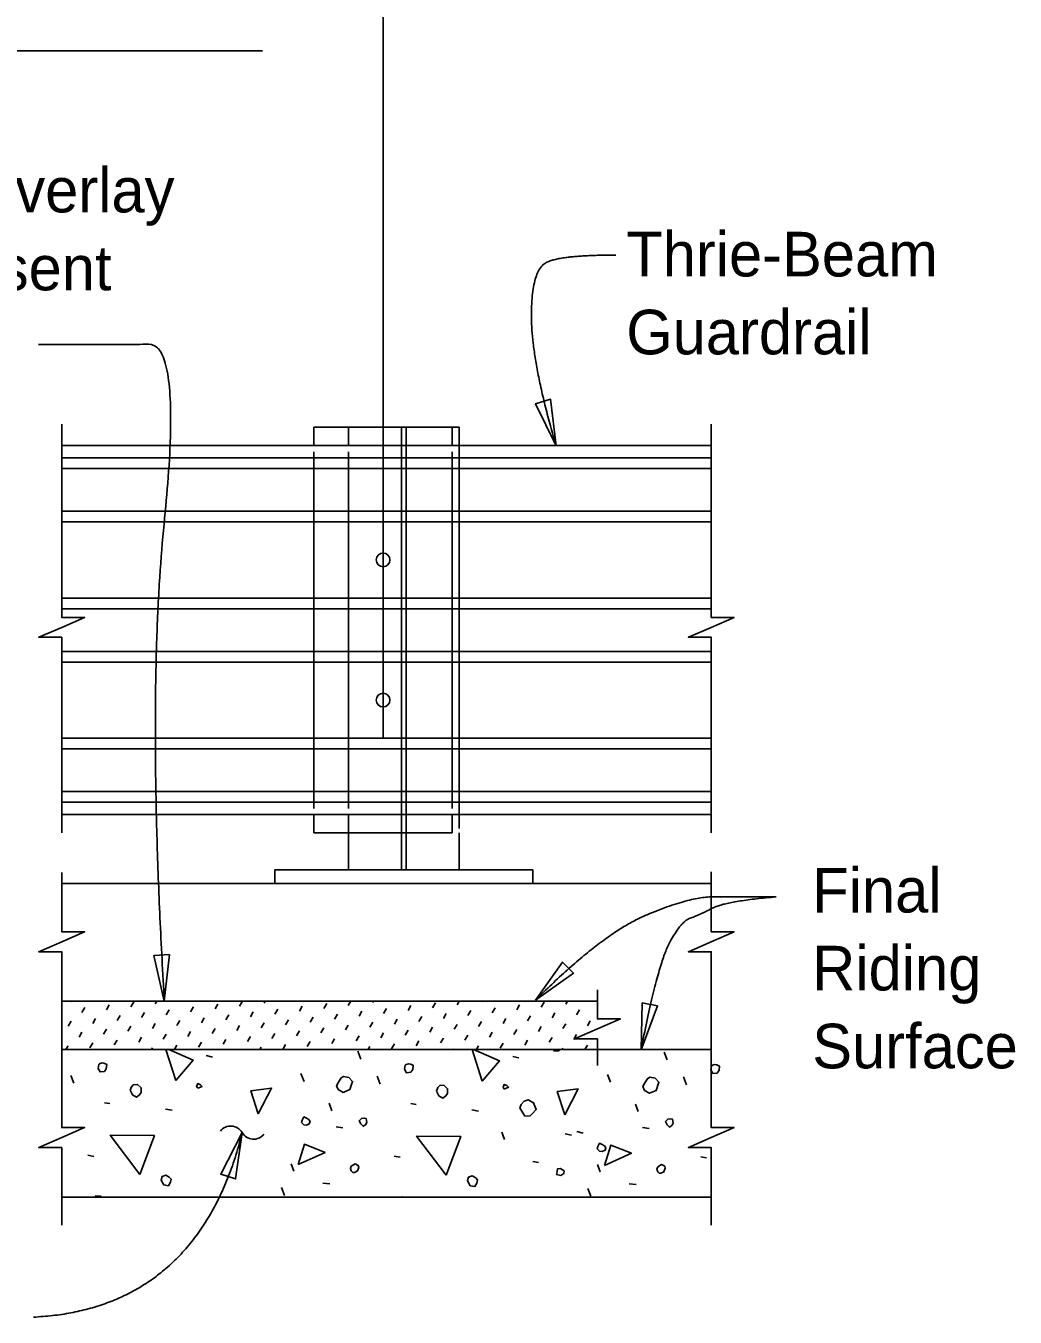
# Model space of a CAD drawing. Extents: x 21516.9 to 21589, y 56154.7 to 56194.3.
# Drawn here: x 21532.46 to 21536.94, y 56170.16 to 56176 of the extents above; entities that cross this region are included whole.
import ezdxf

# ---------------------------------------------------------------- set-up
doc = ezdxf.new("R2010")
doc.units = 0
for name, color, linetype in [('AdhocPoint_dp', 7, 'Continuous'), ('Border', 7, 'Continuous'), ('Patterning', 7, 'Continuous'), ('PlotBorder_dp', 7, 'Continuous'), ('TextMisc', 7, 'Continuous')]:
    doc.layers.add(name, color=color, linetype=linetype)

msp = doc.modelspace()

# ---------------------------------------------------------------- linework, layer by layer
at = {"layer": 'AdhocPoint_dp'}
for p, q in [((21532.6268, 56172.1237), (21535.5624, 56172.1237)), ((21535.0481, 56171.5927), (21532.6268, 56171.5927)), ((21535.5624, 56171.3737), (21532.6268, 56171.3737)), ((21532.6268, 56170.707), (21535.5624, 56170.707))]:
    msp.add_line(p, q, dxfattribs=at)
at = {"layer": 'Border'}
for p, q in [((21534.1627, 56172.1863), (21534.1627, 56174.1863)), ((21534.1835, 56172.1863), (21534.1835, 56174.1863)), ((21534.4231, 56174.1863), (21534.4231, 56172.3733)), ((21533.9231, 56174.0744), (21533.9231, 56172.4625))]:
    msp.add_line(p, q, dxfattribs=at)
at = {"layer": 'Patterning'}
for p, q in [((21533.7668, 56174.1863), (21534.3918, 56174.1863)), ((21533.7668, 56174.1863), (21533.7668, 56174.1029)), ((21534.3918, 56174.1863), (21534.3918, 56174.1029)), ((21533.7668, 56174.0744), (21533.7668, 56172.4625)), ((21534.3918, 56174.0744), (21534.3918, 56172.4625)), ((21533.7668, 56172.3529), (21533.7668, 56172.4363)), ((21534.3918, 56172.3529), (21534.3918, 56172.4363)), ((21533.7668, 56172.3529), (21534.3918, 56172.3529)), ((21532.6693, 56171.5899), (21532.6709, 56171.5927)), ((21532.7181, 56171.5411), (21532.7311, 56171.5635)), ((21532.8287, 56171.554), (21532.8417, 56171.5764)), ((21532.9394, 56171.567), (21532.9523, 56171.5894)), ((21533.05, 56171.58), (21533.0573, 56171.5927)), ((21533.2095, 56171.5441), (21533.2224, 56171.5665)), ((21533.3201, 56171.5571), (21533.3331, 56171.5794)), ((21533.4307, 56171.57), (21533.4437, 56171.5924)), ((21533.5414, 56171.583), (21533.547, 56171.5927)), ((21533.5902, 56171.5341), (21533.6032, 56171.5565)), ((21533.7008, 56171.5471), (21533.7138, 56171.5695)), ((21533.8115, 56171.5601), (21533.8244, 56171.5825)), ((21533.9221, 56171.573), (21533.9335, 56171.5927)), ((21534.0327, 56171.586), (21534.0366, 56171.5927)), ((21534.0816, 56171.5372), (21534.0945, 56171.5596)), ((21534.1922, 56171.5501), (21534.2052, 56171.5725)), ((21534.3028, 56171.5631), (21534.3158, 56171.5855)), ((21534.4135, 56171.5761), (21534.4231, 56171.5927)), ((21534.5241, 56171.589), (21534.5262, 56171.5927)), ((21534.5729, 56171.5402), (21534.5859, 56171.5626)), ((21534.6836, 56171.5532), (21534.6965, 56171.5755)), ((21534.7942, 56171.5661), (21534.8072, 56171.5885)), ((21534.9048, 56171.5791), (21534.9127, 56171.5927)), ((21535.0155, 56171.592), (21535.0158, 56171.5927)), ((21532.6563, 56171.4793), (21532.6693, 56171.5017)), ((21532.7669, 56171.4922), (21532.7799, 56171.5146)), ((21532.8776, 56171.5052), (21532.8905, 56171.5276)), ((21532.9882, 56171.5182), (21533.0012, 56171.5406)), ((21533.0988, 56171.5311), (21533.1118, 56171.5535)), ((21533.1477, 56171.4823), (21533.1606, 56171.5047)), ((21533.2583, 56171.4953), (21533.2713, 56171.5176)), ((21533.3689, 56171.5082), (21533.3819, 56171.5306)), ((21533.4796, 56171.5212), (21533.4925, 56171.5436)), ((21533.639, 56171.4853), (21533.652, 56171.5077)), ((21533.7497, 56171.4983), (21533.7626, 56171.5207)), ((21533.8603, 56171.5112), (21533.8733, 56171.5336)), ((21533.9709, 56171.5242), (21533.9839, 56171.5466)), ((21534.0198, 56171.4754), (21534.0327, 56171.4978)), ((21534.1304, 56171.4883), (21534.1434, 56171.5107)), ((21534.241, 56171.5013), (21534.254, 56171.5237)), ((21534.3517, 56171.5143), (21534.3646, 56171.5367)), ((21534.4623, 56171.5272), (21534.4753, 56171.5496)), ((21534.5111, 56171.4784), (21534.5241, 56171.5008)), ((21534.6218, 56171.4914), (21534.6347, 56171.5137)), ((21534.7324, 56171.5043), (21534.7454, 56171.5267)), ((21534.843, 56171.5173), (21534.856, 56171.5397)), ((21534.9537, 56171.5302), (21534.9666, 56171.5526)), ((21535.0025, 56171.4814), (21535.0155, 56171.5038)), ((21532.7051, 56171.4304), (21532.7181, 56171.4528)), ((21532.8158, 56171.4434), (21532.8287, 56171.4658)), ((21532.9264, 56171.4564), (21532.9394, 56171.4788)), ((21533.037, 56171.4693), (21533.05, 56171.4917)), ((21533.0859, 56171.4205), (21533.0988, 56171.4429)), ((21533.1965, 56171.4335), (21533.2095, 56171.4558)), ((21533.3071, 56171.4464), (21533.3201, 56171.4688)), ((21533.4178, 56171.4594), (21533.4307, 56171.4818)), ((21533.5284, 56171.4723), (21533.5414, 56171.4947)), ((21533.5772, 56171.4235), (21533.5902, 56171.4459)), ((21533.6879, 56171.4365), (21533.7008, 56171.4589)), ((21533.7985, 56171.4494), (21533.8115, 56171.4718)), ((21533.9091, 56171.4624), (21533.9221, 56171.4848)), ((21534.0686, 56171.4265), (21534.0816, 56171.4489)), ((21534.1792, 56171.4395), (21534.1922, 56171.4619)), ((21534.2899, 56171.4525), (21534.3028, 56171.4749)), ((21534.4005, 56171.4654), (21534.4135, 56171.4878)), ((21534.4493, 56171.4166), (21534.4623, 56171.439)), ((21534.56, 56171.4296), (21534.5729, 56171.4519)), ((21534.6706, 56171.4425), (21534.6836, 56171.4649)), ((21534.7812, 56171.4555), (21534.7942, 56171.4779)), ((21534.8919, 56171.4684), (21534.9048, 56171.4908)), ((21534.9407, 56171.4196), (21534.9537, 56171.442)), ((21532.6463, 56171.3737), (21532.6563, 56171.391)), ((21532.754, 56171.3816), (21532.7669, 56171.404)), ((21532.8646, 56171.3946), (21532.8776, 56171.417)), ((21532.9752, 56171.4075), (21532.9882, 56171.4299)), ((21533.0328, 56171.3737), (21533.037, 56171.3811)), ((21533.1359, 56171.3738), (21533.1477, 56171.3941)), ((21533.2453, 56171.3846), (21533.2583, 56171.407)), ((21533.356, 56171.3976), (21533.3689, 56171.42)), ((21533.4666, 56171.4106), (21533.4796, 56171.4329)), ((21533.5224, 56171.3738), (21533.5284, 56171.3841)), ((21533.6261, 56171.3747), (21533.639, 56171.3971)), ((21533.7367, 56171.3876), (21533.7497, 56171.41)), ((21533.8473, 56171.4006), (21533.8603, 56171.423)), ((21533.958, 56171.4136), (21533.9709, 56171.436)), ((21534.0121, 56171.3739), (21534.0198, 56171.3871)), ((21534.1174, 56171.3777), (21534.1304, 56171.4001)), ((21534.2281, 56171.3907), (21534.241, 56171.4131)), ((21534.3387, 56171.4036), (21534.3517, 56171.426)), ((21534.5017, 56171.3739), (21534.5111, 56171.3901)), ((21534.6088, 56171.3807), (21534.6218, 56171.4031)), ((21534.7194, 56171.3937), (21534.7324, 56171.4161)), ((21534.8301, 56171.4066), (21534.843, 56171.429)), ((21534.8883, 56171.374), (21534.8919, 56171.3802)), ((21534.9914, 56171.374), (21535.0025, 56171.3932)), ((21533.2803, 56171.3465), (21533.3086, 56171.3395)), ((21533.909, 56171.3739), (21533.9091, 56171.3742)), ((21533.9786, 56171.3306), (21533.9645, 56171.366)), ((21534.3986, 56171.3739), (21534.4005, 56171.3772)), ((21534.665, 56171.343), (21534.6933, 56171.3359)), ((21535.3633, 56171.3271), (21535.3491, 56171.3624)), ((21533.7223, 56171.2299), (21533.7081, 56171.2652)), ((21532.6817, 56171.2217), (21532.6675, 56171.257)), ((21534.0664, 56171.2181), (21534.0522, 56171.2535)), ((21535.107, 56171.2263), (21535.0928, 56171.2617)), ((21535.451, 56171.2146), (21535.4369, 56171.2499)), ((21532.8196, 56171.1333), (21532.8443, 56171.1297)), ((21533.0953, 56171.105), (21533.1254, 56171.0997)), ((21533.8478, 56171.0973), (21533.8354, 56171.1309)), ((21534.2043, 56171.1297), (21534.229, 56171.1262)), ((21534.48, 56171.1014), (21534.5101, 56171.0961)), ((21535.2325, 56171.0937), (21535.2201, 56171.1273)), ((21533.8666, 56171.0254), (21533.8967, 56171.0201)), ((21534.6285, 56170.9671), (21534.6161, 56171.0007)), ((21534.9025, 56170.9936), (21534.9308, 56170.9865)), ((21534.9549, 56171.0036), (21534.9832, 56170.9965)), ((21535.2513, 56171.0219), (21535.2813, 56171.0166)), ((21532.7453, 56170.8964), (21532.7718, 56170.8911)), ((21533.6763, 56170.8245), (21533.6639, 56170.8581)), ((21534.13, 56170.8928), (21534.1565, 56170.8875)), ((21534.7558, 56170.8681), (21534.7823, 56170.8628)), ((21535.5147, 56170.8893), (21535.5412, 56170.884)), ((21535.061, 56170.821), (21535.0486, 56170.8546)), ((21533.6339, 56170.7149), (21533.6197, 56170.7503)), ((21533.8065, 56170.7709), (21533.8383, 56170.7673)), ((21535.0186, 56170.7114), (21535.0044, 56170.7467)), ((21535.1912, 56170.7673), (21535.223, 56170.7638))]:
    msp.add_line(p, q, dxfattribs=at)
for points in [[(21533.1431, 56171.234), (21533.0976, 56171.3737)], [(21533.1115, 56171.3737), (21533.2209, 56171.326), (21533.1431, 56171.234)], [(21534.5278, 56171.2305), (21534.4812, 56171.3737)], [(21534.4881, 56171.3737), (21534.6055, 56171.3224), (21534.5278, 56171.2305)], [(21534.8499, 56171.3737), (21534.8524, 56171.3678), (21534.8489, 56171.3713)], [(21534.8524, 56171.3678), (21534.8736, 56171.3678), (21534.8796, 56171.3737)], [(21532.7913, 56171.2888), (21532.8001, 56171.2729), (21532.8196, 56171.2747), (21532.8284, 56171.2871), (21532.8302, 56171.3065), (21532.8178, 56171.3118), (21532.809, 56171.3136), (21532.7984, 56171.31), (21532.7948, 56171.3065), (21532.7913, 56171.2888)], [(21534.176, 56171.2853), (21534.1848, 56171.2694), (21534.2043, 56171.2712), (21534.2131, 56171.2835), (21534.2149, 56171.303), (21534.2025, 56171.3083), (21534.1936, 56171.31), (21534.183, 56171.3065), (21534.1795, 56171.303), (21534.176, 56171.2853)], [(21535.5606, 56171.2818), (21535.5695, 56171.2658), (21535.5889, 56171.2676), (21535.5978, 56171.28), (21535.5995, 56171.2994), (21535.5872, 56171.3047), (21535.5783, 56171.3065), (21535.5677, 56171.303), (21535.5642, 56171.2994), (21535.5606, 56171.2818)], [(21532.9362, 56171.1898), (21532.9469, 56171.1686), (21532.9645, 56171.158), (21532.9787, 56171.1686), (21532.9857, 56171.1792), (21532.9857, 56171.2004), (21532.9698, 56171.2163), (21532.9504, 56171.2146), (21532.9416, 56171.2057), (21532.9362, 56171.1898)], [(21533.2421, 56171.1987), (21533.2615, 56171.2075), (21533.2544, 56171.2146), (21533.2421, 56171.2199), (21533.2368, 56171.2075), (21533.2421, 56171.1987)], [(21533.8761, 56171.1927), (21533.8991, 56171.1804), (21533.9291, 56171.1927), (21533.9415, 56171.2299), (21533.9238, 56171.2475), (21533.9008, 56171.2528), (21533.8902, 56171.2458), (21533.8778, 56171.2263), (21533.869, 56171.2104), (21533.8761, 56171.1927)], [(21534.3209, 56171.1863), (21534.3315, 56171.1651), (21534.3492, 56171.1545), (21534.3634, 56171.1651), (21534.3704, 56171.1757), (21534.3704, 56171.1969), (21534.3545, 56171.2128), (21534.3351, 56171.211), (21534.3262, 56171.2022), (21534.3209, 56171.1863)], [(21534.6268, 56171.1951), (21534.6462, 56171.204), (21534.6391, 56171.211), (21534.6268, 56171.2163), (21534.6214, 56171.204), (21534.6268, 56171.1951)], [(21535.2608, 56171.1892), (21535.2837, 56171.1768), (21535.3138, 56171.1892), (21535.3262, 56171.2263), (21535.3085, 56171.244), (21535.2855, 56171.2493), (21535.2749, 56171.2422), (21535.2625, 56171.2228), (21535.2537, 56171.2069), (21535.2608, 56171.1892)], [(21533.5155, 56171.0831), (21533.4819, 56171.1874), (21533.5756, 56171.1998), (21533.5155, 56171.0831)], [(21534.6975, 56171.1103), (21534.7204, 56171.0732), (21534.7434, 56171.0749), (21534.7523, 56171.0838), (21534.7717, 56171.1032), (21534.7593, 56171.1333), (21534.7346, 56171.1474), (21534.7169, 56171.1403), (21534.7028, 56171.1262), (21534.6975, 56171.1103)], [(21534.9001, 56171.0796), (21534.8665, 56171.1839), (21534.9602, 56171.1963), (21534.9001, 56171.0796)], [(21533.7212, 56171.0342), (21533.7336, 56171.0324), (21533.7459, 56171.0377), (21533.7495, 56171.0483), (21533.7442, 56171.0571), (21533.7336, 56171.0642), (21533.7212, 56171.0695), (21533.7141, 56171.0554), (21533.7106, 56171.0448), (21533.7212, 56171.0342)], [(21533.978, 56171.0378), (21533.9886, 56171.0272), (21533.9992, 56171.0343), (21534.0063, 56171.0449), (21534.0027, 56171.0626), (21533.9939, 56171.0643), (21533.9815, 56171.0626), (21533.9709, 56171.0519), (21533.978, 56171.0378)], [(21535.3627, 56171.0343), (21535.3733, 56171.0237), (21535.3839, 56171.0307), (21535.3909, 56171.0413), (21535.3874, 56171.059), (21535.3786, 56171.0608), (21535.3662, 56171.059), (21535.3556, 56171.0484), (21535.3627, 56171.0343)], [(21532.9804, 56170.8098), (21532.8461, 56170.9865), (21533.0459, 56170.9848), (21532.9804, 56170.8098)], [(21534.3651, 56170.8062), (21534.2308, 56170.983), (21534.4305, 56170.9812), (21534.3651, 56170.8062)], [(21533.6951, 56170.854), (21533.7234, 56170.9459), (21533.8171, 56170.9088), (21533.6951, 56170.854)], [(21535.0575, 56170.9152), (21535.0698, 56170.9134), (21535.0822, 56170.9187), (21535.0857, 56170.9293), (21535.0804, 56170.9382), (21535.0698, 56170.9453), (21535.0575, 56170.9506), (21535.0504, 56170.9364), (21535.0469, 56170.9258), (21535.0575, 56170.9152)], [(21535.0798, 56170.8504), (21535.1081, 56170.9423), (21535.2018, 56170.9052), (21535.0798, 56170.8504)], [(21533.9426, 56170.8186), (21533.9497, 56170.8186), (21533.9638, 56170.8257), (21533.9691, 56170.8416), (21533.9674, 56170.8504), (21533.9532, 56170.8575), (21533.9356, 56170.8469), (21533.932, 56170.8363), (21533.9356, 56170.8257), (21533.9426, 56170.8186)], [(21533.0794, 56170.7779), (21533.0883, 56170.762), (21533.1095, 56170.7585), (21533.1183, 56170.7744), (21533.1219, 56170.7886), (21533.113, 56170.7974), (21533.0971, 56170.8062), (21533.0812, 56170.8009), (21533.0759, 56170.785), (21533.0794, 56170.7779)], [(21534.4641, 56170.7744), (21534.473, 56170.7585), (21534.4942, 56170.755), (21534.503, 56170.7709), (21534.5065, 56170.785), (21534.4977, 56170.7939), (21534.4818, 56170.8027), (21534.4659, 56170.7974), (21534.4606, 56170.7815), (21534.4641, 56170.7744)], [(21534.8636, 56170.8098), (21534.8831, 56170.8045), (21534.8955, 56170.8133), (21534.8972, 56170.8257), (21534.8937, 56170.8292), (21534.8795, 56170.8363), (21534.8672, 56170.8345), (21534.8654, 56170.8221), (21534.8636, 56170.8098)], [(21535.3273, 56170.8151), (21535.3344, 56170.8151), (21535.3485, 56170.8221), (21535.3538, 56170.838), (21535.3521, 56170.8469), (21535.3379, 56170.854), (21535.3202, 56170.8434), (21535.3167, 56170.8327), (21535.3202, 56170.8221), (21535.3273, 56170.8151)], [(21532.8047, 56170.707), (21532.8037, 56170.7108), (21532.7807, 56170.7125), (21532.7788, 56170.707)], [(21534.1884, 56170.707), (21534.1883, 56170.7072), (21534.1654, 56170.709), (21534.1647, 56170.707)]]:
    msp.add_lwpolyline(points, dxfattribs=at)
at = {"layer": 'PlotBorder_dp'}
for p, q in [((21534.0793, 56172.7784), (21534.0793, 56187.0198)), ((21533.5339, 56175.8862), (21528.2397, 56175.8862))]:
    msp.add_line(p, q, dxfattribs=at)
for points in [[(21534.8611, 56174.1021), (21534.8361, 56174.3118), (21534.7684, 56174.2918)], [(21533.0907, 56171.5926), (21533.1136, 56171.8026), (21533.0431, 56171.7984)], [(21534.7678, 56171.5968), (21534.9399, 56171.7191), (21534.89, 56171.769)], [(21535.2451, 56171.3732), (21535.3198, 56171.5708), (21535.2506, 56171.5844)], [(21533.443, 56170.9985), (21533.4125, 56170.7895), (21533.3454, 56170.8112)]]:
    msp.add_lwpolyline(points, close=True, dxfattribs=at)
for points in [[(21532.6268, 56172.3532), (21532.6268, 56173.2364), (21532.5234, 56173.2364), (21532.6268, 56173.2814), (21532.7301, 56173.3264), (21532.6268, 56173.3264), (21532.6268, 56174.1994)], [(21535.5623, 56172.3532), (21535.5623, 56173.2364), (21535.459, 56173.2364), (21535.5623, 56173.2814), (21535.6657, 56173.3264), (21535.5623, 56173.3264), (21535.5623, 56174.1994)], [(21532.6268, 56171.3458), (21532.6268, 56171.8158), (21532.5234, 56171.8158), (21532.6268, 56171.8608), (21532.7301, 56171.9058), (21532.6268, 56171.9058), (21532.6268, 56172.1738)], [(21535.5623, 56171.3458), (21535.5623, 56171.8158), (21535.459, 56171.8158), (21535.5623, 56171.8608), (21535.6657, 56171.9058), (21535.5623, 56171.9058), (21535.5623, 56172.1767)], [(21535.0481, 56171.3018), (21535.0481, 56171.4226), (21534.9448, 56171.4226), (21535.0481, 56171.4676), (21535.1515, 56171.5126), (21535.0481, 56171.5126), (21535.0481, 56171.6432)], [(21532.6268, 56170.5807), (21532.6268, 56170.9313), (21532.5234, 56170.9313), (21532.6268, 56170.9763), (21532.7301, 56171.0213), (21532.6268, 56171.0213), (21532.6268, 56171.3458)], [(21535.5623, 56170.5807), (21535.5623, 56170.9313), (21535.459, 56170.9313), (21535.5623, 56170.9763), (21535.6657, 56171.0213), (21535.5623, 56171.0213), (21535.5623, 56171.3458)]]:
    msp.add_lwpolyline(points, dxfattribs=at)
for centre, start, end in [((21533.3906, 56170.9688), 30.00813, 141.73535), ((21533.4938, 56171.0284), 210.00813, 321.73535)]:
    msp.add_arc(centre, 0.0596, start, end, dxfattribs=at)
for points in [[(21535.1315, 56174.9637), (21534.8912, 56174.9637), (21534.7498, 56174.9), (21534.7498, 56174.4794), (21534.8611, 56174.102)], [(21532.5225, 56174.56), (21532.8721, 56174.56), (21533.1718, 56174.56), (21533.0095, 56172.9609), (21533.0907, 56171.5927)], [(21535.8561, 56172.0634), (21535.6653, 56172.0634), (21535.4604, 56172.0634), (21535.0646, 56171.8937), (21534.7678, 56171.5968)], [(21535.8561, 56172.0634), (21535.6303, 56172.0449), (21535.5066, 56171.9813), (21535.4236, 56171.9513), (21535.3193, 56171.7515), (21535.2451, 56171.3732)], [(21533.443, 56170.9985), (21533.242, 56170.2025), (21532.4994, 56170.1647)]]:
    msp.add_open_spline(points, degree=2, dxfattribs=at)
at = {"layer": 'TextMisc'}
for p, q in [((21533.9231, 56174.1863), (21534.4231, 56174.1863)), ((21533.9231, 56174.1863), (21533.9231, 56174.1029)), ((21535.5624, 56174.1029), (21532.6268, 56174.1029)), ((21532.6268, 56174.0473), (21535.5624, 56174.0473)), ((21532.6268, 56173.9991), (21535.5624, 56173.9991)), ((21532.6268, 56173.8063), (21535.5624, 56173.8063)), ((21532.6268, 56173.7581), (21535.5624, 56173.7581)), ((21532.6268, 56173.4141), (21535.5624, 56173.4141)), ((21532.6268, 56173.3659), (21535.5624, 56173.3659)), ((21532.6268, 56173.1731), (21535.5624, 56173.1731)), ((21532.6268, 56173.1249), (21535.5624, 56173.1249)), ((21532.6268, 56172.781), (21535.5624, 56172.781)), ((21532.6268, 56172.7328), (21535.5624, 56172.7328)), ((21532.6268, 56172.5399), (21535.5624, 56172.5399)), ((21532.6268, 56172.4917), (21535.5624, 56172.4917)), ((21535.5624, 56172.4362), (21532.6268, 56172.4362)), ((21533.9231, 56172.4363), (21533.9231, 56172.1863)), ((21534.4231, 56172.3529), (21534.4231, 56172.1863)), ((21533.5898, 56172.1863), (21534.7564, 56172.1863)), ((21533.5898, 56172.1238), (21533.5898, 56172.1863)), ((21533.9231, 56172.1863), (21534.4231, 56172.1863)), ((21534.7564, 56172.1863), (21534.7564, 56172.1238)), ((21533.5898, 56172.1238), (21534.7564, 56172.1238))]:
    msp.add_line(p, q, dxfattribs=at)
for centre in [(21534.0793, 56173.5862), (21534.0793, 56172.953)]:
    msp.add_circle(centre, 0.0312, dxfattribs=at)

# ---------------------------------------------------------------- texts
at = {"layer": 'PlotBorder_dp'}
for s, p in [('Asphalt Overlay', (21531.2336, 56175.1564)), ('Thrie-Beam ', (21535.1783, 56174.867)), ('when present', (21531.2336, 56174.8044)), ('Guardrail', (21535.1783, 56174.515)), ('Final ', (21536.0188, 56171.993)), ('Riding ', (21536.0188, 56171.641)), ('Surface', (21536.0188, 56171.289))]:
    msp.add_text(s, height=0.2016, dxfattribs=at).set_placement(p)

doc.saveas('drawing.dxf')
